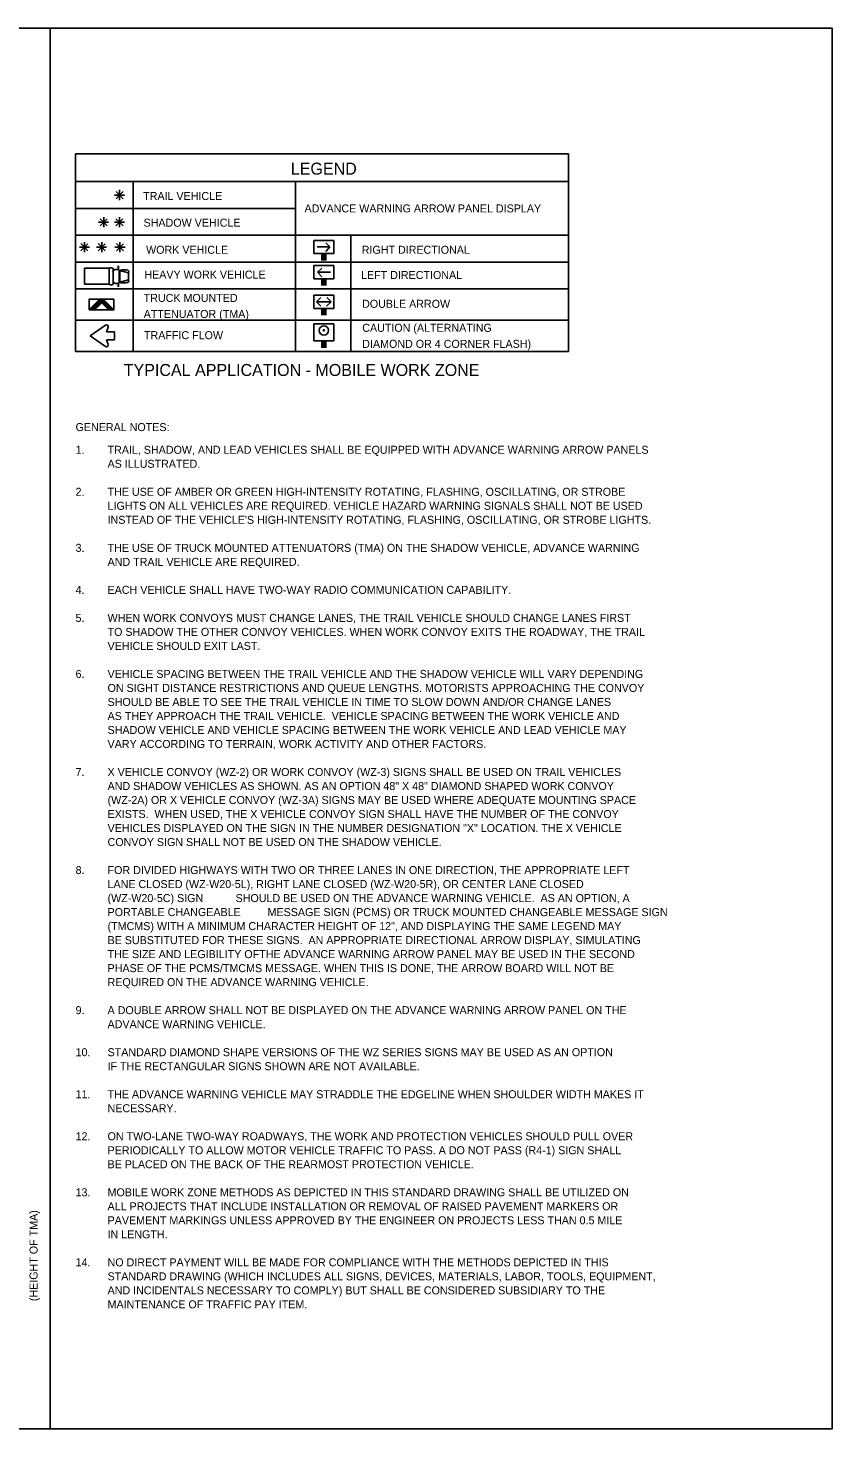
# Model space of a CAD drawing. Extents: x 1806907 to 1812607, y 675071 to 676228.
# Drawn here: x 1812004 to 1812607, y 675071 to 676121 of the extents above; entities that cross this region are included whole.
import ezdxf

# ---------------------------------------------------------------- set-up
doc = ezdxf.new("R2010")
doc.units = 0
doc.layers.add('DSN_DRFT_Named-Boundary', color=7, linetype='Continuous')
doc.layers.add('Working Level 1', color=7, linetype='Continuous')

msp = doc.modelspace()

# ---------------------------------------------------------------- linework, layer by layer
at = {"layer": 'DSN_DRFT_Named-Boundary'}
msp.add_line((1812606.7, 676098.5), (1812606.7, 676121.2), dxfattribs=at)
msp.add_lwpolyline([(1810956.7, 675071.2), (1812606.7, 675071.2), (1812606.7, 676121.2), (1810956.7, 676121.2)], close=True, dxfattribs=at)
at = {"layer": 'Working Level 1'}
for p, q in [((1812020.3, 676121.2), (1812020.3, 675071.2)), ((1812039.4, 676026.9), (1812039.4, 675878.7)), ((1812039.4, 676026.9), (1812409.1, 676026.9)), ((1812409.1, 675878.7), (1812409.1, 676026.9)), ((1812039.4, 676006.1), (1812409.1, 676006.1)), ((1812082.7, 676006.5), (1812082.7, 675878.7)), ((1812082.7, 676006.5), (1812082.7, 675878.7)), ((1812204.4, 676006.1), (1812204.4, 675878.7)), ((1812072.4, 675996), (1812068.7, 675996)), ((1812072.4, 675996), (1812069.8, 675998.7)), ((1812072.4, 675996), (1812069.8, 675993.3)), ((1812072.4, 675996), (1812072.4, 675999.8)), ((1812072.4, 675995.9), (1812075, 675998.6)), ((1812072.4, 675996), (1812075.1, 675993.3)), ((1812072.4, 675996), (1812072.4, 675992.2)), ((1812072.4, 675996), (1812076.2, 675996)), ((1812039.4, 675986), (1812204.4, 675986)), ((1812060.5, 675975.7), (1812056.7, 675975.7)), ((1812060.5, 675975.7), (1812057.8, 675978.3)), ((1812060.5, 675975.7), (1812057.8, 675973)), ((1812060.4, 675975.6), (1812063.1, 675978.3)), ((1812060.5, 675975.7), (1812060.5, 675979.4)), ((1812060.5, 675975.7), (1812063.1, 675973)), ((1812060.5, 675975.7), (1812060.5, 675971.9)), ((1812060.5, 675975.7), (1812064.2, 675975.7)), ((1812072.3, 675975.7), (1812068.5, 675975.7)), ((1812072.3, 675975.7), (1812069.6, 675978.3)), ((1812072.3, 675975.7), (1812069.6, 675973)), ((1812072.2, 675975.6), (1812074.9, 675978.3)), ((1812072.3, 675975.7), (1812072.3, 675979.4)), ((1812072.3, 675975.7), (1812075, 675973)), ((1812072.3, 675975.7), (1812072.3, 675971.9)), ((1812072.3, 675975.7), (1812076.1, 675975.7)), ((1812039.4, 675965.9), (1812409.1, 675965.9)), ((1812046.1, 675956.9), (1812043.4, 675959.6)), ((1812046, 675956.9), (1812048.7, 675959.5)), ((1812046.1, 675956.9), (1812046.1, 675960.7)), ((1812059, 675956.9), (1812056.3, 675959.6)), ((1812058.9, 675956.9), (1812061.6, 675959.5)), ((1812059, 675956.9), (1812059, 675960.7)), ((1812072.7, 675956.9), (1812070, 675959.6)), ((1812072.6, 675956.9), (1812075.3, 675959.5)), ((1812072.7, 675956.9), (1812072.7, 675960.7)), ((1812409.1, 675965.9), (1812204.4, 675965.9)), ((1812218.1, 675962), (1812218.1, 675952.1)), ((1812233.1, 675962), (1812218.1, 675962)), ((1812218.1, 675962), (1812233.1, 675962)), ((1812230.2, 675957.1), (1812227, 675960.2)), ((1812233.1, 675962), (1812233.1, 675952.1)), ((1812245.8, 675965.9), (1812245.8, 675878.7)), ((1812046.1, 675956.9), (1812042.3, 675956.9)), ((1812046.1, 675956.9), (1812043.4, 675954.3)), ((1812046.1, 675956.9), (1812048.7, 675954.3)), ((1812046.1, 675956.9), (1812046.1, 675953.2)), ((1812046.1, 675956.9), (1812049.8, 675956.9)), ((1812059, 675956.9), (1812055.2, 675956.9)), ((1812059, 675956.9), (1812056.3, 675954.3)), ((1812059, 675956.9), (1812061.6, 675954.3)), ((1812059, 675956.9), (1812059, 675953.2)), ((1812059, 675956.9), (1812062.7, 675956.9)), ((1812072.7, 675956.9), (1812068.9, 675956.9)), ((1812072.7, 675956.9), (1812070, 675954.3)), ((1812072.7, 675956.9), (1812075.4, 675954.3)), ((1812072.7, 675956.9), (1812072.7, 675953.2)), ((1812072.7, 675956.9), (1812076.5, 675956.9)), ((1812218.1, 675952.1), (1812233.1, 675952.1)), ((1812220.6, 675957.1), (1812230.2, 675957.1)), ((1812224.1, 675952.1), (1812224.1, 675947)), ((1812224.8, 675952.1), (1812224.8, 675947)), ((1812225.6, 675952.1), (1812225.6, 675947)), ((1812226.3, 675952.1), (1812226.3, 675947)), ((1812230.2, 675957.1), (1812227, 675953.8)), ((1812227.1, 675952.1), (1812227.1, 675947)), ((1812039.4, 675945.8), (1812409.1, 675945.8)), ((1812039.4, 675945.8), (1812204.4, 675945.8)), ((1812046.1, 675941.1), (1812064.6, 675941.1)), ((1812046.1, 675929.1), (1812046.1, 675941.1)), ((1812064.6, 675935.1), (1812064.6, 675941.1)), ((1812067.5, 675935.1), (1812067.5, 675941.1)), ((1812071.3, 675941.4), (1812071.3, 675942.9)), ((1812071.5, 675940), (1812071.5, 675942.9)), ((1812071.7, 675940), (1812071.7, 675942.9)), ((1812072.2, 675935.1), (1812072.2, 675939.4)), ((1812072.6, 675939.4), (1812079.1, 675937.6)), ((1812072.6, 675935.1), (1812072.6, 675939.4)), ((1812079.1, 675935.1), (1812079.1, 675937.6)), ((1812218.1, 675943.1), (1812218.1, 675933.1)), ((1812233.1, 675943.1), (1812218.1, 675943.1)), ((1812218.1, 675943.1), (1812233.1, 675943.1)), ((1812220.9, 675938.1), (1812224.1, 675941.3)), ((1812230.6, 675938.1), (1812220.9, 675938.1)), ((1812220.9, 675938.1), (1812224.2, 675934.8)), ((1812233.1, 675943.1), (1812233.1, 675933.1)), ((1812046.1, 675929.1), (1812064.6, 675929.1)), ((1812064.6, 675935.1), (1812064.6, 675929.1)), ((1812067.5, 675935.1), (1812067.5, 675929.1)), ((1812071.3, 675928.7), (1812071.3, 675927.2)), ((1812071.5, 675930.1), (1812071.5, 675927.2)), ((1812071.7, 675930.1), (1812071.7, 675927.2)), ((1812072.2, 675935.1), (1812072.2, 675930.7)), ((1812072.6, 675935.1), (1812072.6, 675930.7)), ((1812072.6, 675930.7), (1812079.1, 675932.5)), ((1812079.1, 675935.1), (1812079.1, 675932.5)), ((1812218.1, 675933.1), (1812233.1, 675933.1)), ((1812224.1, 675933.1), (1812224.1, 675928.1)), ((1812224.8, 675933.1), (1812224.8, 675928.1)), ((1812225.6, 675933.1), (1812225.6, 675928.1)), ((1812226.3, 675933.1), (1812226.3, 675928.1)), ((1812227.1, 675933.1), (1812227.1, 675928.1)), ((1812039.4, 675925.7), (1812409.1, 675925.7)), ((1812049.6, 675910), (1812057.7, 675918.1)), ((1812068.2, 675910), (1812060.2, 675918.1)), ((1812218.1, 675921), (1812218.1, 675911.1)), ((1812233.1, 675921), (1812218.1, 675921)), ((1812218.1, 675921), (1812233.1, 675921)), ((1812220.2, 675916), (1812223.4, 675919.2)), ((1812231, 675916), (1812227.8, 675919.2)), ((1812233.1, 675921), (1812233.1, 675911.1)), ((1812053.6, 675910), (1812059, 675915.3)), ((1812064.3, 675910), (1812059, 675915.3)), ((1812218.1, 675911.1), (1812233.1, 675911.1)), ((1812220.2, 675916), (1812223.4, 675912.8)), ((1812220.9, 675916), (1812230.2, 675916)), ((1812224.1, 675911.1), (1812224.1, 675906)), ((1812224.8, 675911.1), (1812224.8, 675906)), ((1812225.6, 675911.1), (1812225.6, 675906)), ((1812226.3, 675911.1), (1812226.3, 675906)), ((1812227.1, 675911.1), (1812227.1, 675906)), ((1812231, 675916), (1812227.7, 675912.8)), ((1812039.4, 675902.3), (1812409.1, 675902.3)), ((1812050.3, 675890.5), (1812061.9, 675898.4)), ((1812062.6, 675893.5), (1812063.8, 675897)), ((1812218.1, 675899.6), (1812218.1, 675886.7)), ((1812233.1, 675899.6), (1812218.1, 675899.6)), ((1812218.1, 675899.6), (1812233.1, 675899.6)), ((1812233.1, 675899.6), (1812233.1, 675886.7)), ((1812050.3, 675890.5), (1812061.9, 675882.5)), ((1812068.7, 675893.5), (1812062.6, 675893.5)), ((1812068.7, 675887.4), (1812062.6, 675887.4)), ((1812062.6, 675887.4), (1812063.8, 675883.9)), ((1812068.7, 675893.5), (1812068.7, 675887.4)), ((1812218.1, 675886.7), (1812233.1, 675886.7)), ((1812224.1, 675886.7), (1812224.1, 675881.6)), ((1812224.8, 675886.7), (1812224.8, 675881.6)), ((1812225.6, 675886.7), (1812225.6, 675881.6)), ((1812226.3, 675886.7), (1812226.3, 675881.6)), ((1812227.1, 675886.7), (1812227.1, 675881.6)), ((1812039.4, 675878.7), (1812409.1, 675878.7))]:
    msp.add_line(p, q, dxfattribs=at)
msp.add_lwpolyline([(1812068.2, 675918.1), (1812068.2, 675910), (1812049.6, 675910), (1812049.6, 675918.1)], close=True, dxfattribs=at)
for points in [[(1812050, 675910.4), (1812061.3, 675916.9)], [(1812051, 675911.4), (1812061, 675917.2)], [(1812052, 675912.4), (1812060.8, 675917.5)], [(1812053, 675913.4), (1812060.5, 675917.7)], [(1812054, 675914.4), (1812060.2, 675918)], [(1812055, 675915.4), (1812059.6, 675918.1)], [(1812056, 675916.4), (1812058.9, 675918.1)], [(1812057, 675917.4), (1812058.2, 675918.1)], [(1812059.1, 675915.2), (1812061.6, 675916.7)], [(1812050, 675910), (1812058.5, 675914.9)], [(1812050.7, 675910), (1812057.6, 675913.9)], [(1812051.5, 675910), (1812056.6, 675913)], [(1812052.2, 675910), (1812055.7, 675912)], [(1812053, 675910), (1812054.7, 675911)], [(1812053.7, 675910), (1812053.8, 675910)], [(1812059.3, 675915), (1812061.8, 675916.4)], [(1812059.6, 675914.7), (1812062.1, 675916.1)], [(1812059.9, 675914.4), (1812062.4, 675915.9)], [(1812060.2, 675914.1), (1812062.6, 675915.6)], [(1812060.4, 675913.9), (1812062.9, 675915.3)], [(1812060.7, 675913.6), (1812063.2, 675915)], [(1812061, 675913.3), (1812063.4, 675914.8)], [(1812061.2, 675913.1), (1812063.7, 675914.5)], [(1812061.5, 675912.8), (1812064, 675914.2)], [(1812061.8, 675912.5), (1812064.2, 675914)], [(1812062, 675912.3), (1812064.5, 675913.7)], [(1812062.3, 675912), (1812064.8, 675913.4)], [(1812062.6, 675911.7), (1812065.1, 675913.2)], [(1812062.8, 675911.5), (1812065.3, 675912.9)], [(1812063.1, 675911.2), (1812065.6, 675912.6)], [(1812063.4, 675910.9), (1812065.9, 675912.4)], [(1812063.6, 675910.6), (1812066.1, 675912.1)], [(1812063.9, 675910.4), (1812066.4, 675911.8)], [(1812064.2, 675910.1), (1812066.7, 675911.5)], [(1812064.7, 675910), (1812066.9, 675911.3)], [(1812065.4, 675910), (1812067.2, 675911)], [(1812066.2, 675910), (1812067.5, 675910.7)], [(1812066.9, 675910), (1812067.7, 675910.5)], [(1812067.6, 675910), (1812068, 675910.2)]]:
    msp.add_lwpolyline(points, dxfattribs=at)
for radius in [3.51, 0.437]:
    msp.add_circle((1812225.6, 675894.6), radius, dxfattribs=at)
for centre, radius, start, end in [((1812077.5, 675938.5), 1.8, 331.8801, 28.1199), ((1812077.5, 675931.7), 1.8, 331.8801, 28.1199), ((1812062.6, 675897.4), 1.23, 342.1824, 124.4455), ((1812062.6, 675883.5), 1.23, 235.5546, 17.8176)]:
    msp.add_arc(centre, radius, start, end, dxfattribs=at)
for centre, major_axis, ratio, start_param, end_param in [((1812066, 675941.1), (1.42, 0), 0.269913, 0, 3.141593), ((1812069.8, 675939.1), (2.38, 0.29), 0.503092, 0, 3.141593), ((1812075.9, 675939.3), (3.24, -0.04), 0.2034, 0, 3.141593), ((1812066, 675929.1), (1.42, 0), 0.269913, 3.141593, 6.283185), ((1812069.8, 675931), (2.38, -0.29), 0.503092, 3.141593, 6.283185), ((1812075.9, 675930.8), (3.24, 0.04), 0.2034, 3.141593, 6.283185)]:
    msp.add_ellipse(centre, major_axis=major_axis, ratio=ratio, start_param=start_param, end_param=end_param, dxfattribs=at)

# ---------------------------------------------------------------- texts
for s, height, p in [('LEGEND', 9, (1812200.8, 676011.3)), ('TRAIL VEHICLE', 6, (1812090.1, 675992.3)), ('ADVANCE WARNING ARROW PANEL DISPLAY', 6, (1812211.1, 675983)), ('SHADOW VEHICLE', 6, (1812090.4, 675972.3)), ('WORK VEHICLE', 6, (1812092.3, 675952)), ('RIGHT DIRECTIONAL', 6, (1812254, 675952)), ('HEAVY WORK VEHICLE', 6, (1812091, 675933.4)), ('LEFT DIRECTIONAL', 6, (1812253.5, 675933.1)), ('TRUCK MOUNTED ', 6, (1812090.5, 675915.9)), ('DOUBLE ARROW', 6, (1812254.3, 675911.5)), ('ATTENUATOR (TMA)', 6, (1812090.5, 675903.9)), ('CAUTION (ALTERNATING ', 6, (1812254.4, 675893.5)), ('TRAFFIC FLOW', 6, (1812090.7, 675888)), ('DIAMOND OR 4 CORNER FLASH)', 6, (1812254.4, 675881.5)), ('TYPICAL APPLICATION - MOBILE WORK ZONE', 9, (1812075.5, 675860.4)), ('GENERAL NOTES:', 6, (1812039.4, 675819.1)), ('1. ', 6, (1812039.4, 675802.1)), ('TRAIL, SHADOW, AND LEAD VEHICLES SHALL BE EQUIPPED WITH ADVANCE WARNING ARROW PANELS', 6, (1812063.4, 675802.1)), ('AS ILLUSTRATED. ', 6, (1812063.4, 675791.6)), ('2.', 6, (1812039.4, 675770.6)), ('THE USE OF AMBER OR GREEN HIGH-INTENSITY ROTATING, FLASHING, OSCILLATING, OR STROBE ', 6, (1812063.4, 675770.6)), ('LIGHTS ON ALL VEHICLES ARE REQUIRED. VEHICLE HAZARD WARNING SIGNALS SHALL NOT BE USED ', 6, (1812063.4, 675760.1)), ("INSTEAD OF THE VEHICLE'S HIGH-INTENSITY ROTATING, FLASHING, OSCILLATING, OR STROBE LIGHTS.", 6, (1812063.4, 675749.6)), ('3. ', 6, (1812039.4, 675728.6)), ('THE USE OF TRUCK MOUNTED ATTENUATORS (TMA) ON THE SHADOW VEHICLE, ADVANCE WARNING', 6, (1812063.4, 675728.6)), ('AND TRAIL VEHICLE ARE REQUIRED.', 6, (1812063.4, 675718.1)), ('4. ', 6, (1812039.4, 675697.1)), ('EACH VEHICLE SHALL HAVE TWO-WAY RADIO COMMUNICATION CAPABILITY. ', 6, (1812063.4, 675697.1)), ('5. ', 6, (1812039.4, 675676.1)), ('WHEN WORK CONVOYS MUST CHANGE LANES, THE TRAIL VEHICLE SHOULD CHANGE LANES FIRST ', 6, (1812063.4, 675676.1)), ('TO SHADOW THE OTHER CONVOY VEHICLES. WHEN WORK CONVOY EXITS THE ROADWAY, THE TRAIL', 6, (1812063.4, 675665.6)), ('VEHICLE SHOULD EXIT LAST.', 6, (1812063.4, 675655.1)), ('6. ', 6, (1812039.4, 675634.1)), ('VEHICLE SPACING BETWEEN THE TRAIL VEHICLE AND THE SHADOW VEHICLE WILL VARY DEPENDING ', 6, (1812063.4, 675634.1)), ('ON SIGHT DISTANCE RESTRICTIONS AND QUEUE LENGTHS. MOTORISTS APPROACHING THE CONVOY ', 6, (1812063.4, 675623.6)), ('SHOULD BE ABLE TO SEE THE TRAIL VEHICLE IN TIME TO SLOW DOWN AND/OR CHANGE LANES ', 6, (1812063.4, 675613.1)), ('AS THEY APPROACH THE TRAIL VEHICLE.  VEHICLE SPACING BETWEEN THE WORK VEHICLE AND ', 6, (1812063.4, 675602.6)), ('SHADOW VEHICLE AND VEHICLE SPACING BETWEEN THE WORK VEHICLE AND LEAD VEHICLE MAY ', 6, (1812063.4, 675592.1)), ('VARY ACCORDING TO TERRAIN, WORK ACTIVITY AND OTHER FACTORS.', 6, (1812063.4, 675581.6)), ('7. ', 6, (1812039.4, 675560.6)), ('X VEHICLE CONVOY (WZ-2) OR WORK CONVOY (WZ-3) SIGNS SHALL BE USED ON TRAIL VEHICLES', 6, (1812063.4, 675560.6)), ('AND SHADOW VEHICLES AS SHOWN. AS AN OPTION 48" X 48" DIAMOND SHAPED WORK CONVOY', 6, (1812063.4, 675550.1)), ('(WZ-2A) OR X VEHICLE CONVOY (WZ-3A) SIGNS MAY BE USED WHERE ADEQUATE MOUNTING SPACE', 6, (1812063.4, 675539.6)), ('EXISTS.  WHEN USED, THE X VEHICLE CONVOY SIGN SHALL HAVE THE NUMBER OF THE CONVOY', 6, (1812063.4, 675529.1)), ('VEHICLES DISPLAYED ON THE SIGN IN THE NUMBER DESIGNATION "X" LOCATION. THE X VEHICLE', 6, (1812063.4, 675518.6)), ('CONVOY SIGN SHALL NOT BE USED ON THE SHADOW VEHICLE.', 6, (1812063.4, 675508.1)), ('8.', 6, (1812039.4, 675487.1)), ('FOR DIVIDED HIGHWAYS WITH TWO OR THREE LANES IN ONE DIRECTION, THE APPROPRIATE LEFT ', 6, (1812063.4, 675487.1)), ('LANE CLOSED (WZ-W20-5L), RIGHT LANE CLOSED (WZ-W20-5R), OR CENTER LANE CLOSED ', 6, (1812063.4, 675476.6)), ('(WZ-W20-5C) SIGN', 6, (1812063.4, 675466.1)), ('SHOULD BE USED ON THE ADVANCE WARNING VEHICLE.  AS AN OPTION, A ', 6, (1812159.4, 675466.1)), ('PORTABLE CHANGEABLE', 6, (1812063.4, 675455.6)), ('MESSAGE SIGN (PCMS) OR TRUCK MOUNTED CHANGEABLE MESSAGE SIGN ', 6, (1812183.4, 675455.6)), ('(TMCMS) WITH A MINIMUM CHARACTER HEIGHT OF 12", AND DISPLAYING THE SAME LEGEND MAY ', 6, (1812063.4, 675445.1)), ('BE SUBSTITUTED FOR THESE SIGNS.  AN APPROPRIATE DIRECTIONAL ARROW DISPLAY, SIMULATING ', 6, (1812063.4, 675434.6)), ('THE SIZE AND LEGIBILITY OFTHE ADVANCE WARNING ARROW PANEL MAY BE USED IN THE SECOND ', 6, (1812063.4, 675424.1)), ('PHASE OF THE PCMS/TMCMS MESSAGE. WHEN THIS IS DONE, THE ARROW BOARD WILL NOT BE ', 6, (1812063.4, 675413.6)), ('REQUIRED ON THE ADVANCE WARNING VEHICLE.', 6, (1812063.4, 675403.1)), ('9.', 6, (1812039.4, 675382.1)), ('A DOUBLE ARROW SHALL NOT BE DISPLAYED ON THE ADVANCE WARNING ARROW PANEL ON THE ', 6, (1812063.4, 675382.1)), ('ADVANCE WARNING VEHICLE. ', 6, (1812063.4, 675371.6)), ('10.', 6, (1812039.4, 675350.6)), ('STANDARD DIAMOND SHAPE VERSIONS OF THE WZ SERIES SIGNS MAY BE USED AS AN OPTION ', 6, (1812063.4, 675350.6)), ('IF THE RECTANGULAR SIGNS SHOWN ARE NOT AVAILABLE.', 6, (1812063.4, 675340.1)), ('11.', 6, (1812039.4, 675319.1)), ('THE ADVANCE WARNING VEHICLE MAY STRADDLE THE EDGELINE WHEN SHOULDER WIDTH MAKES IT ', 6, (1812063.4, 675319.1)), ('NECESSARY.', 6, (1812063.4, 675308.6)), ('12. ', 6, (1812039.4, 675287.6)), ('ON TWO-LANE TWO-WAY ROADWAYS, THE WORK AND PROTECTION VEHICLES SHOULD PULL OVER', 6, (1812063.4, 675287.6)), ('PERIODICALLY TO ALLOW MOTOR VEHICLE TRAFFIC TO PASS. A DO NOT PASS (R4-1) SIGN SHALL ', 6, (1812063.4, 675277.1)), ('BE PLACED ON THE BACK OF THE REARMOST PROTECTION VEHICLE.', 6, (1812063.4, 675266.6)), ('13.', 6, (1812039.4, 675245.6)), ('MOBILE WORK ZONE METHODS AS DEPICTED IN THIS STANDARD DRAWING SHALL BE UTILIZED ON ', 6, (1812063.4, 675245.6)), ('ALL PROJECTS THAT INCLUDE INSTALLATION OR REMOVAL OF RAISED PAVEMENT MARKERS OR ', 6, (1812063.4, 675235.1)), ('PAVEMENT MARKINGS UNLESS APPROVED BY THE ENGINEER ON PROJECTS LESS THAN 0.5 MILE ', 6, (1812063.4, 675224.6)), ('IN LENGTH.', 6, (1812063.4, 675214.1)), ('14.', 6, (1812039.4, 675193.1)), ('NO DIRECT PAYMENT WILL BE MADE FOR COMPLIANCE WITH THE METHODS DEPICTED IN THIS ', 6, (1812063.4, 675193.1)), ('STANDARD DRAWING (WHICH INCLUDES ALL SIGNS, DEVICES, MATERIALS, LABOR, TOOLS, EQUIPMENT, ', 6, (1812063.4, 675182.6)), ('AND INCIDENTALS NECESSARY TO COMPLY) BUT SHALL BE CONSIDERED SUBSIDIARY TO THE ', 6, (1812063.4, 675172.1)), ('MAINTENANCE OF TRAFFIC PAY ITEM.', 6, (1812063.4, 675161.6))]:
    msp.add_text(s, height=height, dxfattribs=at).set_placement(p)
msp.add_text('(HEIGHT OF TMA)', height=6, rotation=90, dxfattribs=at).set_placement((1812010.9, 675167))

doc.saveas('drawing.dxf')
